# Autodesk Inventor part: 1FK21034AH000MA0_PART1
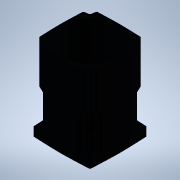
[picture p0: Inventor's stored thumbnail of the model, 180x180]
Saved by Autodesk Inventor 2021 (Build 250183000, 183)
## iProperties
Created: 2025-04
Part Number: 1FK21034AH000MA0_PART1
Material: Generic
Catalog Web Link: www.3dfindit.com
Description: -Servo synchronous motor
Document SubType Name: Modeling
Designer: psAdmin
Mass: 88.22 g
Surface Area: 399.791 cm^2
Volume: 88.22 cm^3
Density: 1 g/cm^3
Appearance: PSOLRGB-176-176-176
Category: PARTsolutions
Title: 1FK21034AH000MA0_PART1
Author: Cadenas PARTsolutions
Comments: Servo synchronous motor
Sending System: PARTsolutions
Preprocessor: ST-DEVELOPER v19.3
PSOL_IDENT_0: {$CADENAS_DATA/23d-libs/siemens_ag/_cat_/ec/b7/1fk21034ah000ma0.prj},213 {VTYP=3D},{NB=1FK21034AH000
PSOL_IDENT_1: MA0_PART1},{LINA=1FK21034AH000MA0_PART1},{NN=1FK21034AH000MA0_PART1},{NOPRJ=TRUE},{DATE=19.08.2025 1
PSOL_IDENT_2: 4:01:05},{GEOMDATE=30.07.2025 02:01:02},{VERSION=},{LINEID=10},{WBVAR=},{WBNUMERIC=}  {NB=1FK21034AH
PSOL_IDENT_3: 000MA0_PART1},{LINA=1FK21034AH000MA0_PART1},{KT=DUMMY},{PREVIEW=../../../_pool_/7c/50/p_d211_xx_0093
PSOL_IDENT_4: 2j.png},{DESCSHORT=SIMOTICS S-1FK2 HD, SINAMICS S210 3AC 400V-480V, 1.01 Nm, 4500 rpm},{DESCLONG=SIM
PSOL_IDENT_5: OTICS S-1FK2 HD servo motor M0=1.27 Nm; PN = 0.48 kW at nN=4500 rpm (380-480 V); PN = 0.3 kW at nN=2
PSOL_IDENT_6: 500 rpm (200-240 V); degree of protection IP64; cylindrical shaft D14 x 30 mm; absolute encoder 22-b
PSOL_IDENT_7: it + 12-bit multiturn (encoder AM22DQC); with OCC interface; plug size M17, rotatable; SIMOTICS S-1F
PSOL_IDENT_8: K2 servomotorfor a wide range of uses in industrial environments. SIMOTICS S‑1FK2 servomotors are co
PSOL_IDENT_9: mpact synchronous motors with a high dynamic performance that set themselves apart as a result of th
PSOL_IDENT_10: eir high power density, degree of protection and overload capability. The motors are available in tw
PSOL_IDENT_11: o variants: as High Dynamic variant (highest dynamic performance as a result of the low intrinsic mo
PSOL_IDENT_12: ment of inertia for applications demanding a high dynamic performance with low moved masses) - and a
PSOL_IDENT_13: s Compact variant (precise and stable closed-loop control for medium up to large moved masses as a r
PSOL_IDENT_14: esult of a medium intrinsic moment of inertia). SIMOTICSS‑1FK2 servomotors fully exploit their stren
PSOL_IDENT_15: gths in a system with the SINAMICSS210 frequency converter and simple connection using the one cable
PSOL_IDENT_16: connection (OCC). Advantages include the short control and positioning times, fast and precise corr
PSOL_IDENT_17: ection of disturbing quantities as well as stable control with a high dynamic performance. The servo
PSOL_IDENT_18: motors can be configured to address a wide range of requirements. For example with and without hold
PSOL_IDENT_19: ing brake, IP64 or IP65 degree of protection, singleturn or multiturn absolute encoders - to name ju
PSOL_IDENT_20: st a few. Further, the servomotors are available in different shaft heights extending from 20 to 100
PSOL_IDENT_21: . A shaft sealing ring is available to achieve an IP65 degree of protection and for subsequent mount
PSOL_IDENT_22: ing at the motor or as spare part. SIMOTICS - the optimum motor for each and every motion control ap
PSOL_IDENT_23: plication.},{INTNO=4034106444822},{SUPPLIERALTNO=1FK2103-4AH00-0MA0},{MANUID=1FK21034AH000MA0},{MANU
PSOL_IDENT_24: NAME=Siemens},{MANUTYPEDESC=SYNCHRONOUS MOTOR 1FK2 HD 1,27 NM},{AAU732=SIMOTICS},{AAO057=S-1FK2},{AA
PSOL_IDENT_25: U734=SIMOTICS S-1FK2 HD servo motor M0=1.27 Nm; PN = 0.48 kW at nN=4500 rpm (380-480 V); PN = 0.3 kW
PSOL_IDENT_26: at nN=2500 rpm (200-240 V); degree of protection IP64; cylindrical shaft D14 x 30 mm; absolute enco
PSOL_IDENT_27: der 22-bit + 12-bit multiturn (encoder AM22DQC); with OCC interface; plug size M17, rotatable;},{AAW
PSOL_IDENT_28: 338=SYNCHRONOUS MOTOR 1FK2 HD 1,27 NM},{AAO742=SIMOTICS},{AAO663=4034106444822},{NOCUPEROU=1},{PRICE
PSOL_IDENT_29: QUANTITY=1},{QUANTITYMIN=1},{QUANTITYINT=1},{CTN=85015100},{COO=RO},{AAO676=1FK2103-4AH00-0MA0},{AAO
PSOL_IDENT_30: 677=Siemens AG},{ORDERUNIT=C62},{CONTENTUNIT=C62}
NB: 1FK21034AH000MA0_PART1
NT: Servo synchronous motor
NBSYN: $MANUID._PART1
LINA: 1FK21034AH000MA0_PART1
CATALOG: SIEMENS
PREVIEW: ../../../_pool_/7c/50/p_d211_xx_00932j.png
DESCSHORT: SIMOTICS S-1FK2 HD, SINAMICS S210 3AC 400V-480V, 1.01 Nm, 4500 rpm
DESCLONG: SIMOTICS S-1FK2 HD servo motor M0=1.27 Nm; PN = 0.48 kW at nN=4500 rpm (380-480 V); PN = 0.3 kW at nN=2500 rpm (200-240 V); degree of protection IP64; cylindric
INTNO: 4034106444822
SUPPLIERALTNO: 1FK2103-4AH00-0MA0
MANUID: 1FK21034AH000MA0
MANUNAME: Siemens
MANUTYPEDESC: SYNCHRONOUS MOTOR 1FK2 HD 1,27 NM
AAU732: SIMOTICS
AAO057: S-1FK2
AAU734: SIMOTICS S-1FK2 HD servo motor M0=1.27 Nm; PN = 0.48 kW at nN=4500 rpm (380-480 V); PN = 0.3 kW at nN=2500 rpm (200-240 V); degree of protection IP64; cylindric
AAW338: SYNCHRONOUS MOTOR 1FK2 HD 1,27 NM
AAO742: SIMOTICS
AAO663: 4034106444822.0
NOCUPEROU: 1
PRICEQUANTITY: 1
QUANTITYMIN: 1
QUANTITYINT: 1
CTN: 85015100
COO: RO
ARTICLENO: 1FK21034AH000MA0_PART1
BOMINFO: 1FK21034AH000MA0_PART1
CREATOR: CADENAS GmbH
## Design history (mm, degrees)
feature "2025_04_17_15_01_37_0158"
node "ECLASS_CAX_IMPORTER_001_CP_0_XY"
node "ECLASS_CAX_IMPORTER_001_CP_0_YZ"
node "ECLASS_CAX_IMPORTER_001_CP_0_ZX"
node "ECLASS_CAX_IMPORTER_001_CP_0_X"
node "ECLASS_CAX_IMPORTER_001_CP_0_Y"
node "ECLASS_CAX_IMPORTER_001_CP_0_Z"
node "ECLASS_CAX_IMPORTER_001_CP_0_Center"
node "ECLASS_CAX_IMPORTER_001_CP_1_XY"
node "ECLASS_CAX_IMPORTER_001_CP_1_YZ"
node "ECLASS_CAX_IMPORTER_001_CP_1_ZX"
node "ECLASS_CAX_IMPORTER_001_CP_1_X"
node "ECLASS_CAX_IMPORTER_001_CP_1_Y"
node "ECLASS_CAX_IMPORTER_001_CP_1_Z"
node "ECLASS_CAX_IMPORTER_001_CP_1_Center"
body "Solid1"
